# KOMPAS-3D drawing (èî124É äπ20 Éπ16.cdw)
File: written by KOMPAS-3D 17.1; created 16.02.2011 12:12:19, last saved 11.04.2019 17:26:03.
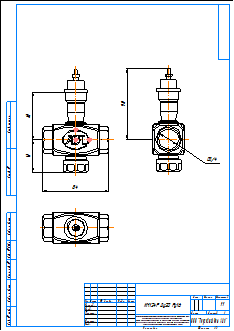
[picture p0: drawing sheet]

Title block, sheet 1: name: КМ124Р Ду20 Ру16; material: Внимание! Данный продукт является объектом авторского права ООО «Торговый Дом АДЛ». / Запрещается изменение, копирование, распространение / (в том числе путем копирования на другие сайты и ресурсы в Интернете) / или любое иное использование информации и объектов без предварительного / согласия правообладателя (ООО «Торговый Дом АДЛ»).; scale: 1:1; sheets: 1; organisation: ООО "Торговый дом АДЛ"; sheet format: A3; stored path: \\adlc.lan\data\АДЛ_ПКД\3D-модели\ADL production\Клапаны ГРАНРЕГ\Двухходовой клапан KM124P\KOMPAS 2D\КМ124Р Ду20 Ру16.cdw

Views: Спереди 1, Проекционный вид 2, Проекционный вид 3
Dimensions and other numbers on the sheet: 84; 41; 61; 90; 1:1; 1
